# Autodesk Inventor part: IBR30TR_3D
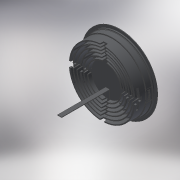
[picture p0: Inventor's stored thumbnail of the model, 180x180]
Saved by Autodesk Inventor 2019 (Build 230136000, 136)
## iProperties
Created: 2020-04
Part Number: IBR30TR_3D
Material: Generic
Document SubType Name: Modeling
Designer: EL
Density: 1 g/cm^3
Appearance: Default
Author: EL
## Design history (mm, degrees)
derived "IGBR30TR-XX-V.iam"
node "Solid108.ipt:1"
body "Srf1"
node "Solid128.ipt:1"
node "PA90.ipt:1"
node "P110008_01-Piastrino UL LBXS RING 12x.ipt:1"
node "Spacer for Blade R UL.ipt:1"
node "Solid21_1_test.ipt:1"
node "Solid27_1 (2).ipt:1"
node "IGBR30TR-XX-V.iam_Bodies"
